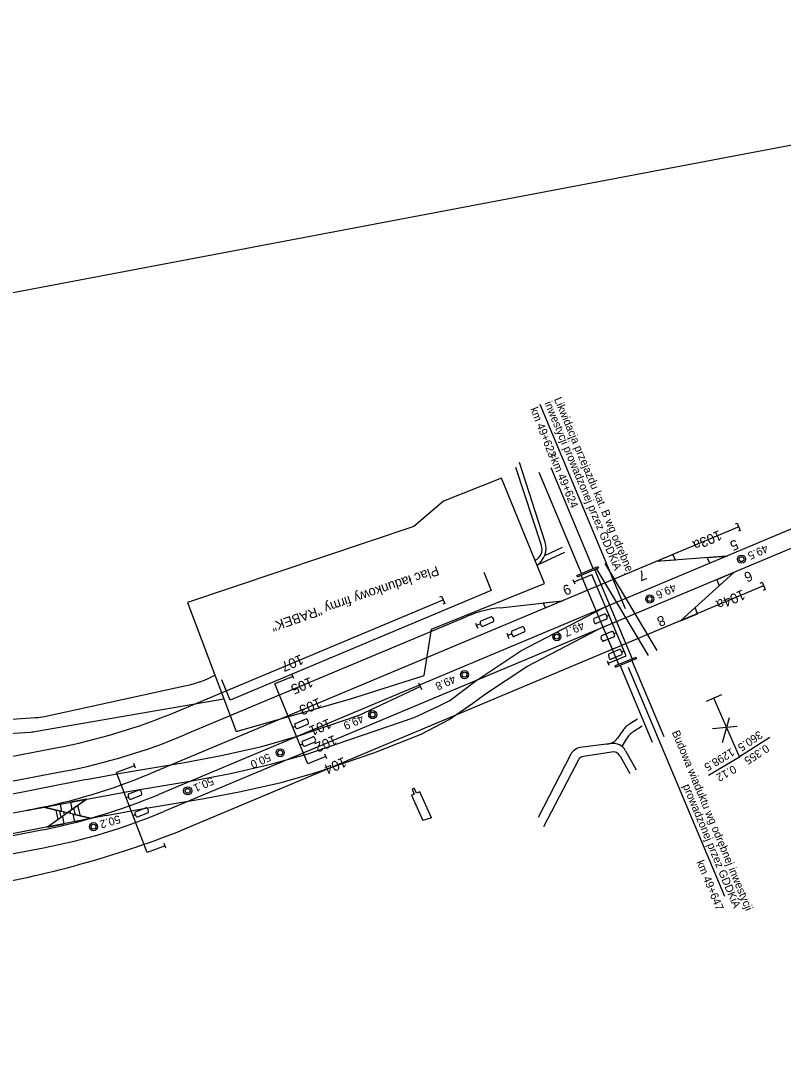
# Model space of a CAD drawing. Extents: x 6541740 to 6566395, y 5525066 to 5530361.
# Drawn here: x 6565985.9 to 6566176.4, y 5527585 to 5527842.5 of the extents above; entities that cross this region are included whole.
import ezdxf

# ---------------------------------------------------------------- set-up
doc = ezdxf.new("R2010")
doc.units = 0
for name, color, linetype in [('ps_wymiarowanie', 7, 'Continuous'), ('TOR_PRZEK_P-komponent', 7, 'Continuous'), ('TOR_PRZEK_P-teren istniejacy', 7, 'Continuous'), ('TOR_PRZEK_P-uklad odniesienia', 7, 'Continuous'), ('TOR_PS_ODW-odwodnienie liniowe', 7, 'Continuous'), ('TOR_PS_ODW-osadniki', 7, 'Continuous'), ('TOR_PS_ODW-osadniki wstepne', 7, 'Continuous'), ('TOR_PS_OPIS_T-opis geometrii -prostopadly', 7, 'Continuous'), ('TOR_PS_OPIS_T-opis geometrii-wzdluz_cz torowa', 7, 'Continuous'), ('TOR_PS_OPIS_T-symbole geometrii', 7, 'Continuous'), ('TOR_PS_P-chodniki i place ładunkowe', 7, 'Continuous'), ('TOR_PS_T-rowy otwarte nieumocnione', 7, 'Continuous'), ('TOR_PS_T-wypelnienia', 7, 'Continuous'), ('TOR_RAMKI-ramka+tabelka 1', 7, 'Continuous'), ('TOR_W-warstwa dodatkowa 2', 7, 'Continuous'), ('TOR_W-warstwa dodatkowa 3', 7, 'Continuous')]:
    doc.layers.add(name, color=color, linetype=linetype)

msp = doc.modelspace()

# ---------------------------------------------------------------- linework, layer by layer
at = {"layer": 'ps_wymiarowanie'}
for p, q in [((6566084.21, 5527650.79), (6566083.65, 5527650.57)), ((6566083.65, 5527650.57), (6566084.21, 5527649.32)), ((6566084.77, 5527649.54), (6566084.21, 5527650.79)), ((6566084.21, 5527649.32), (6566083.5, 5527649.05)), ((6566083.5, 5527649.05), (6566086.34, 5527642.71)), ((6566085.59, 5527649.84), (6566084.77, 5527649.54)), ((6566088.49, 5527643.38), (6566085.59, 5527649.84)), ((6566088.5, 5527643.38), (6566086.34, 5527642.71))]:
    msp.add_line(p, q, dxfattribs=at)
at = {"layer": 'TOR_PRZEK_P-komponent'}
for p, q in [((6566346.99, 5527786.22), (6566020.35, 5527649.24)), ((6566244.47, 5527738.39), (6566021.64, 5527644.94)), ((6566165.26, 5527716.08), (6566018.17, 5527654.4)), ((6566162.26, 5527708.75), (6566144.51, 5527707.38)), ((6566150.71, 5527692.6), (6566163.99, 5527704.64)), ((6566171.45, 5527701.3), (6566025.81, 5527640.17)), ((6566024.74, 5527669.89), (6566091.42, 5527697.85)), ((6566105.69, 5527695.86), (6566121.21, 5527697.61)), ((6566097.45, 5527693.71), (6566026.77, 5527664.07)), ((6565794.57, 5527622.92), (6565994.65, 5527660.84)), ((6565816.3, 5527620.83), (6565996.69, 5527655.03)), ((6565918.52, 5527632.24), (6565988.8, 5527645.56)), ((6565804.55, 5527604.98), (6565990.27, 5527640.19)), ((6565805.38, 5527600.6), (6565991.56, 5527635.89))]:
    msp.add_line(p, q, dxfattribs=at)
for points in [[(6566164.41, 5527716.81), (6566164.87, 5527717), (6566165.64, 5527715.16), (6566165.18, 5527714.96)], [(6566170.61, 5527702.03), (6566171.07, 5527702.23), (6566171.84, 5527700.38), (6566171.38, 5527700.19)], [(6566090.57, 5527698.58), (6566091.03, 5527698.78), (6566091.8, 5527696.93), (6566091.34, 5527696.74)]]:
    msp.add_lwpolyline(points, dxfattribs=at)
for points in [[(6566144.51, 5527707.38), (6566148.74, 5527709.15), (6566149.42, 5527707.76)], [(6566162.26, 5527708.75), (6566158.03, 5527706.98), (6566157.35, 5527708.37)], [(6566163.99, 5527704.64), (6566159.76, 5527702.86), (6566160.35, 5527701.34)], [(6566121.21, 5527697.61), (6566116.98, 5527695.83), (6566116.38, 5527697.06)], [(6566150.71, 5527692.6), (6566154.94, 5527694.37), (6566154.35, 5527695.9)]]:
    msp.add_lwpolyline(points, close=True, dxfattribs=at)
for centre, radius, start, end in [((6566109.05, 5527666.05), 30, 96.423, 112.7516), ((6565966.73, 5527808.22), 150, 280.7292, 292.7516), ((6565968.76, 5527802.4), 150, 280.7316, 292.7516), ((6565961.51, 5527789.52), 146.52, 280.7332, 292.7516), ((6565962.34, 5527787.56), 150, 280.7332, 292.7516), ((6565963.63, 5527783.27), 150, 280.7332, 292.7516), ((6565934.61, 5527871.23), 248.41, 279.3063, 291.5392)]:
    msp.add_arc(centre, radius, start, end, dxfattribs=at)
at = {"layer": 'TOR_PRZEK_P-uklad odniesienia'}
for p, q in [((6566161.16, 5527662.23), (6566162.96, 5527668.43)), ((6566164.87, 5527666.21), (6566158.66, 5527665.6))]:
    msp.add_line(p, q, dxfattribs=at)
at = {"layer": 'TOR_PS_ODW-osadniki'}
for p, q in [((6566160.98, 5527674.13), (6566157.13, 5527672.46)), ((6566172.99, 5527663.44), (6566165.42, 5527658.62)), ((6566157.69, 5527654.05), (6566165.42, 5527658.62))]:
    msp.add_line(p, q, dxfattribs=at)
msp.add_lwpolyline([(6566165.42, 5527658.62), (6566159.05, 5527673.3)], dxfattribs=at)
at = {"layer": 'TOR_PS_ODW-osadniki wstepne'}
msp.add_lwpolyline([(6566101.54, 5527704.78), (6566103.45, 5527700.14), (6566038.25, 5527672.79), (6566036.17, 5527677.85)], dxfattribs=at)
at = {"layer": 'TOR_PS_OPIS_T-opis geometrii -prostopadly'}
for p, q in [((6566124.39, 5527701.74), (6566123.92, 5527702.86)), ((6566124.16, 5527702.3), (6566128.59, 5527704.16)), ((6566137.11, 5527683.85), (6566128.59, 5527704.16)), ((6566131.73, 5527694.28), (6566129.14, 5527693.2)), ((6566132.32, 5527693.77), (6566132.86, 5527693.99)), ((6566099.5, 5527692.02), (6566099.77, 5527691.37)), ((6566099.5, 5527692.02), (6566099.77, 5527691.37)), ((6566100.72, 5527691.82), (6566099.75, 5527691.41)), ((6566099.77, 5527691.37), (6566100.04, 5527690.73)), ((6566099.77, 5527691.37), (6566100.04, 5527690.73)), ((6566103.38, 5527693.6), (6566100.81, 5527692.5)), ((6566103.93, 5527692.31), (6566101.35, 5527691.21)), ((6566132.26, 5527692.99), (6566129.67, 5527691.91)), ((6566107.3, 5527689.5), (6566107.57, 5527688.86)), ((6566107.3, 5527689.5), (6566107.57, 5527688.86)), ((6566108.51, 5527689.31), (6566107.54, 5527688.9)), ((6566107.57, 5527688.86), (6566107.84, 5527688.21)), ((6566107.57, 5527688.86), (6566107.84, 5527688.21)), ((6566111.18, 5527691.09), (6566108.6, 5527689.99)), ((6566111.72, 5527689.8), (6566109.15, 5527688.7)), ((6566133.57, 5527689.9), (6566130.98, 5527688.82)), ((6566134.15, 5527689.39), (6566134.69, 5527689.62)), ((6566134.1, 5527688.6), (6566131.51, 5527687.52)), ((6566132.68, 5527681.99), (6566137.11, 5527683.85)), ((6566135.46, 5527685.39), (6566132.87, 5527684.31)), ((6566135.99, 5527684.09), (6566133.4, 5527683.02)), ((6566136.05, 5527684.87), (6566136.59, 5527685.1)), ((6566132.91, 5527681.43), (6566132.44, 5527682.55)), ((6566053.85, 5527678.72), (6566049.4, 5527676.89)), ((6566054.08, 5527678.16), (6566053.62, 5527679.28)), ((6566057.65, 5527656.86), (6566049.4, 5527676.89)), ((6566054.44, 5527666.2), (6566053.9, 5527665.97)), ((6566054.49, 5527666.98), (6566057.07, 5527668.05)), ((6566055.03, 5527665.69), (6566057.62, 5527666.76)), ((6566056.3, 5527662.57), (6566058.89, 5527663.65)), ((6566056.25, 5527661.79), (6566055.71, 5527661.57)), ((6566056.85, 5527661.28), (6566059.43, 5527662.36)), ((6566062.1, 5527658.69), (6566057.65, 5527656.86)), ((6566062.33, 5527658.13), (6566061.87, 5527659.25)), ((6566062.33, 5527658.13), (6566061.87, 5527659.25)), ((6566014.34, 5527656.39), (6566009.84, 5527654.67)), ((6566014.55, 5527655.82), (6566014.12, 5527656.95)), ((6566017.46, 5527634.69), (6566009.84, 5527654.67)), ((6566012.87, 5527649.35), (6566015.48, 5527650.35)), ((6566012.79, 5527648.57), (6566012.25, 5527648.36)), ((6566013.37, 5527648.05), (6566015.99, 5527649.05)), ((6566014.56, 5527644.9), (6566017.17, 5527645.91)), ((6566014.49, 5527644.12), (6566013.94, 5527643.92)), ((6566015.07, 5527643.6), (6566017.68, 5527644.6)), ((6566021.95, 5527636.4), (6566017.46, 5527634.69)), ((6566022.17, 5527635.83), (6566021.73, 5527636.97)), ((6566022.17, 5527635.83), (6566021.73, 5527636.97))]:
    msp.add_line(p, q, dxfattribs=at)
for centre, major_axis, start_param, end_param in [((6566131.99, 5527693.63), (0.264, -0.648), 0.003914, 3.145491), ((6566101.08, 5527691.86), (0.271, -0.646), 3.145506, 6.287107), ((6566103.65, 5527692.96), (0.271, -0.646), 0.003914, 3.145491), ((6566129.41, 5527692.56), (0.264, -0.648), 3.145506, 6.287107), ((6566108.87, 5527689.34), (0.271, -0.646), 3.145506, 6.287107), ((6566111.45, 5527690.45), (0.271, -0.646), 0.003914, 3.145491), ((6566131.25, 5527688.17), (0.264, -0.648), 3.145506, 6.287107), ((6566133.83, 5527689.25), (0.264, -0.648), 0.003914, 3.145491), ((6566133.14, 5527683.66), (0.264, -0.648), 3.145506, 6.287107), ((6566135.72, 5527684.74), (0.264, -0.648), 0.003914, 3.145491), ((6566054.76, 5527666.33), (0.273, -0.644), 3.137695, 6.279271), ((6566057.35, 5527667.4), (0.273, -0.644), 6.279264, 9.420864), ((6566059.16, 5527663), (0.273, -0.644), 6.279264, 9.420864), ((6566056.57, 5527661.93), (0.273, -0.644), 3.137695, 6.279271), ((6566015.73, 5527649.7), (0.256, -0.652), 6.279264, 9.420864), ((6566013.12, 5527648.7), (0.256, -0.652), 3.137695, 6.279271), ((6566017.43, 5527645.25), (0.256, -0.652), 6.279264, 9.420864), ((6566014.81, 5527644.25), (0.256, -0.652), 3.137695, 6.279271)]:
    msp.add_ellipse(centre, major_axis=major_axis, ratio=0.5, start_param=start_param, end_param=end_param, dxfattribs=at)
at = {"layer": 'TOR_PS_OPIS_T-opis geometrii-wzdluz_cz torowa'}
for p, q in [((6566136.99, 5527695.61), (6566115.62, 5527746.59)), ((6566137.65, 5527681.01), (6566161.7, 5527623.85)), ((6566014.49, 5527644.12), (6566013.94, 5527643.92))]:
    msp.add_line(p, q, dxfattribs=at)
msp.add_lwpolyline([(6565988.57, 5527645.44), (6565987.72, 5527645.27)], dxfattribs=at)
msp.add_ellipse((6566130.92, 5527664.37), major_axis=(5.3, -2.84), ratio=0.692659, start_param=6.202987, end_param=6.241714, dxfattribs=at)
at = {"layer": 'TOR_PS_OPIS_T-symbole geometrii'}
for p, q in [((6566115.97, 5527711.41), (6566109.56, 5527730.86)), ((6566128.93, 5527705.64), (6566118.36, 5527730.8)), ((6566126.01, 5527704.42), (6566115.42, 5527729.62)), ((6566143.75, 5527662.19), (6566135.64, 5527681.5)), ((6566146.59, 5527663.62), (6566138.56, 5527682.73)), ((6566133.32, 5527661.92), (6566132.24, 5527661.79)), ((6566135.64, 5527658.81), (6566138.05, 5527654.44)), ((6566136.98, 5527660.15), (6566139.59, 5527655.39))]:
    msp.add_line(p, q, dxfattribs=at)
msp.add_lwpolyline([(6566116.88, 5527712.2), (6566110.52, 5527732.14)], dxfattribs=at)
for centre, radius, start, end in [((6566112.11, 5527710.68), 5, 303.6127, 17.6778), ((6566113.12, 5527710.47), 3, 294.8391, 18.2379), ((6566133.91, 5527658.47), 3.5, 28.7134, 99.6592), ((6566133.89, 5527657.84), 2, 28.9336, 101.8489)]:
    msp.add_arc(centre, radius, start, end, dxfattribs=at)
at = {"layer": 'TOR_PS_P-chodniki i place ładunkowe'}
msp.add_lwpolyline([(6565514.26, 5527395.47), (6565461.18, 5527675.49), (6566342.4, 5527842.53), (6566395.48, 5527562.51), (6565514.26, 5527395.47)], dxfattribs=at)
at = {"layer": 'TOR_PS_T-rowy otwarte nieumocnione'}
for p, q in [((6566002.34, 5527652.92), (6565974.1, 5527647.33)), ((6566002.33, 5527648.03), (6565992.54, 5527641.08)), ((6566003.58, 5527643.24), (6565991.67, 5527646.02)), ((6565995.23, 5527642.99), (6565994.73, 5527645.3)), ((6565996.01, 5527643.54), (6565995.68, 5527645.08)), ((6565998.41, 5527644.44), (6565998.23, 5527645.12)), ((6565999.61, 5527644.16), (6565999.18, 5527645.8)), ((6566000.81, 5527643.88), (6566000.13, 5527646.47)), ((6565996.79, 5527644.09), (6565996.62, 5527644.86))]:
    msp.add_line(p, q, dxfattribs=at)
for points in [[(6566093.07, 5527672.71), (6566099.54, 5527677.58), (6566110.78, 5527685.07), (6566131.45, 5527695.83)], [(6566098.84, 5527672), (6566102.02, 5527674.32), (6566112.3, 5527681.16), (6566130.06, 5527690.41)], [(6566070.45, 5527668.99), (6566085.69, 5527676.15)], [(6566085.27, 5527676.88), (6566085.37, 5527676.98), (6566085.99, 5527675.49), (6566085.9, 5527675.4)], [(6566004.65, 5527648.48), (6566013.13, 5527650.08), (6566029.13, 5527652.73), (6566038.29, 5527654.46), (6566048.41, 5527656.77), (6566057.36, 5527659.29), (6566071.55, 5527664.13), (6566084.17, 5527668.47), (6566090.41, 5527671.37), (6566093.07, 5527672.71)], [(6566007.23, 5527643.95), (6566015.71, 5527645.55), (6566031.7, 5527648.2), (6566040.86, 5527649.93), (6566050.99, 5527652.24), (6566059.94, 5527654.76), (6566074.12, 5527659.6), (6566085.96, 5527664.3), (6566092.93, 5527667.98), (6566098.84, 5527672)], [(6566002.34, 5527652.92), (6566010.82, 5527654.53), (6566026.82, 5527657.17), (6566035.98, 5527658.91), (6566046.11, 5527661.22), (6566055.06, 5527663.74), (6566070.45, 5527668.99)], [(6565987.32, 5527645.18), (6566004.65, 5527648.48)], [(6566007.23, 5527643.95), (6565967.44, 5527636.18), (6565955.89, 5527632.39), (6565922.93, 5527622.81), (6565908.81, 5527619.03), (6565880.44, 5527613.72), (6565852.88, 5527608.97), (6565828.68, 5527605.11), (6565800.44, 5527603.38)]]:
    msp.add_lwpolyline(points, dxfattribs=at)
for points in [[(6566002.33, 5527648.03), (6565998.31, 5527647.27), (6565998.7, 5527645.46)], [(6565996.15, 5527644.97), (6565995.82, 5527646.8), (6565991.67, 5527646.02)], [(6565996.75, 5527641.9), (6565996.4, 5527643.82), (6565992.54, 5527641.08)], [(6566003.58, 5527643.24), (6565999.37, 5527642.41), (6565999.01, 5527644.3)]]:
    msp.add_lwpolyline(points, close=True, dxfattribs=at)
at = {"layer": 'TOR_PS_T-wypelnienia'}
for p, q in [((6566121.75, 5527709.65), (6566114.88, 5527706.52)), ((6566121.17, 5527710.89), (6566116.77, 5527708.85)), ((6565991.82, 5527668.72), (6566027.2, 5527676.41)), ((6565989.83, 5527665), (6566036.64, 5527673.07)), ((6565962.93, 5527666.69), (6565989.59, 5527668.4)), ((6566140, 5527668.02), (6566138.23, 5527666.95)), ((6566141.1, 5527666.26), (6566139.03, 5527664.97)), ((6565962.46, 5527663.15), (6565988.24, 5527664.81)), ((6566136.3, 5527665.17), (6566134.97, 5527663.26)), ((6566137.16, 5527663.06), (6566136.13, 5527661.38)), ((6566132.24, 5527661.79), (6566126.23, 5527661.07)), ((6566123.3, 5527659.27), (6566115.13, 5527643.42)), ((6566125.2, 5527657.84), (6566116.51, 5527641.1)), ((6566133.48, 5527659.8), (6566126.44, 5527658.73))]:
    msp.add_line(p, q, dxfattribs=at)
msp.add_lwpolyline([(6566116.77, 5527701.88), (6566106.02, 5527728.23), (6566091.49, 5527722.45), (6566084.13, 5527716.14), (6566027.55, 5527697.2), (6566039.72, 5527664.91), (6566068.06, 5527673), (6566086.64, 5527678.95), (6566088.47, 5527690.47)], close=True, dxfattribs=at)
for points in [[(6566131.78, 5527706.92), (6566144.81, 5527685.2)], [(6566129.64, 5527705.63), (6566142.67, 5527683.91)]]:
    msp.add_lwpolyline(points, dxfattribs=at)
for centre, radius, start, end in [((6566020.82, 5527705.73), 30, 282.2754, 296.9493), ((6565988.63, 5527683.37), 15, 273.6739, 282.2754), ((6565987.28, 5527679.78), 15, 273.6739, 279.7831), ((6566126.69, 5527657.07), 1.68, 98.6251, 152.5462)]:
    msp.add_arc(centre, radius, start, end, dxfattribs=at)
for centre, major_axis, start_param, end_param in [((6566146.53, 5527658.92), (-10.59, 5.68), 5.89296, 6.201577), ((6566129.85, 5527666.39), (5.3, -2.84), 5.504379, 6.201577), ((6566147.58, 5527657.09), (-10.59, 5.68), 5.925874, 6.241714), ((6566128.62, 5527656.47), (-5.3, 2.84), 5.504379, 6.294034)]:
    msp.add_ellipse(centre, major_axis=major_axis, ratio=0.692659, start_param=start_param, end_param=end_param, dxfattribs=at)
at = {"layer": 'TOR_RAMKI-ramka+tabelka 1'}
for centre, radius in [((6566165.94, 5527707.99), 1.01), ((6566165.94, 5527707.99), 0.606), ((6566143.02, 5527698.05), 1.01), ((6566143.02, 5527698.05), 0.606), ((6566119.82, 5527688.64), 1.01), ((6566119.82, 5527688.64), 0.606), ((6566096.74, 5527679.14), 1.01), ((6566096.74, 5527679.14), 0.606), ((6566073.82, 5527669.16), 1.01), ((6566073.82, 5527669.16), 0.606), ((6566050.7, 5527659.64), 1.01), ((6566050.7, 5527659.64), 0.606), ((6566027.59, 5527650.12), 1.01), ((6566027.59, 5527650.12), 0.606), ((6566004.06, 5527641.16), 1.01), ((6566004.06, 5527641.16), 0.606)]:
    msp.add_circle(centre, radius, dxfattribs=at)
at = {"layer": 'TOR_W-warstwa dodatkowa 2'}
for p, q in [((6566124.97, 5527703.62), (6566130.22, 5527705.83)), ((6566138.67, 5527683.14), (6566129.3, 5527705.44)), ((6566135.26, 5527681.71), (6566125.89, 5527704.01)), ((6566134.34, 5527681.32), (6566139.59, 5527683.53))]:
    msp.add_line(p, q, dxfattribs=at)
for points in [[(6566124.97, 5527703.62), (6566124.84, 5527703.93), (6566130.09, 5527706.13), (6566130.22, 5527705.83)], [(6566134.34, 5527681.32), (6566134.47, 5527681.01), (6566139.72, 5527683.22), (6566139.59, 5527683.53)]]:
    msp.add_lwpolyline(points, dxfattribs=at)

# ---------------------------------------------------------------- texts
at = {"layer": 'TOR_PRZEK_P-teren istniejacy'}
msp.add_text('Plac ładunkowy firmy "RABEK"', height=2.3918, rotation=198.8542, dxfattribs=at).set_placement((6566089.87, 5527706.36))
at = {"layer": 'TOR_PS_ODW-odwodnienie liniowe'}
for s, p in [('103a', (6566160.34, 5527715.29)), ('104a', (6566166.19, 5527700.44)), ('107', (6566055.83, 5527684.26)), ('105', (6566058.25, 5527678.61)), ('103', (6566060.33, 5527673.41)), ('101', (6566062.81, 5527668.24)), ('102', (6566064.22, 5527664.13)), ('104', (6566066.59, 5527658.64))]:
    msp.add_text(s, height=2.5, rotation=203.2582, dxfattribs=at).set_placement(p)
at = {"layer": 'TOR_PS_ODW-osadniki'}
for s, rotation, p in [('360.5', 213.8442, (6566170.36, 5527665.23)), ('1298.5', 211.3577, (6566163.39, 5527660.87)), ('0.355', 212.6121, (6566172.05, 5527661.81)), ('0.12', 208.7192, (6566163.98, 5527656.6))]:
    msp.add_text(s, height=2, rotation=rotation, dxfattribs=at).set_placement(p)
at = {"layer": 'TOR_PS_OPIS_T-opis geometrii-wzdluz_cz torowa'}
for s, height, rotation, p in [('Likwidacja przejazdu kat. B wg odrębnej ', 2, 292.7256, (6566119.07, 5527747.97)), ('km 49+623', 2, 291.4625, (6566113.12, 5527745.51)), ('inwestycji prowadzonej przez GDDKiA', 2, 292.7256, (6566116.68, 5527746.97)), ('=km 49+624', 2, 292.7256, (6566117.68, 5527734.27)), ('A', 0.00199, 202.752, (6566139.99, 5527699.41)), ('B', 0.00199, 202.6985, (6566120.01, 5527691)), ('Budowa wiaduktu wg odrębnej inwestycji', 2, 292.4773, (6566148.51, 5527664.74)), (' prowadzonej przez GDDKiA', 2, 292.4773, (6566150.96, 5527652.05)), ('km 49+647', 2, 292.4773, (6566154.63, 5527632.32))]:
    msp.add_text(s, height=height, rotation=rotation, dxfattribs=at).set_placement(p)
at = {"layer": 'TOR_RAMKI-ramka+tabelka 1'}
for s, rotation, p in [('49.5', 204.1804, (6566172.04, 5527711.71)), ('49.6', 204.1804, (6566149.08, 5527701.94)), ('49.7', 204.1804, (6566126.15, 5527692.46)), ('49.8', 204.1804, (6566094, 5527679.09)), ('49.9', 204.1804, (6566071.04, 5527669.22)), ('50.0', 204.1804, (6566047.8, 5527659.57)), ('50.1', 204.1804, (6566033.56, 5527653.65)), ('50.2', 196.4335, (6566010.45, 5527644.07))]:
    msp.add_text(s, height=2, rotation=rotation, dxfattribs=at).set_placement(p)
at = {"layer": 'TOR_W-warstwa dodatkowa 3'}
for s, p in [('5', (6566164.53, 5527712.99)), ('7', (6566141.57, 5527705.43)), ('6', (6566168.07, 5527705.14)), ('9', (6566122.75, 5527701.86)), ('8', (6566146.3, 5527694.04))]:
    msp.add_text(s, height=2.5, rotation=202.0986, dxfattribs=at).set_placement(p)

doc.saveas('drawing.dxf')
